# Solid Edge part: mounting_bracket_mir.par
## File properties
Author: Haley
Template: Metric Part.par
Last saved by: Lee
Revision: 3
Application: Solid Edge
Accuracy: 0.990
Username: Haley
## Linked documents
mounting_bracket.par
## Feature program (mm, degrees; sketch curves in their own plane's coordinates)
part copy "CopiedPart_1"
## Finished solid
Body 1: solid body, 21 faces, 44 edges, 24 vertices.
  Faces by surface: cylinder 10, torus 6, plane 5
  Edges by curve: circle 22, line 18, intersection 4
Bounding box of the edges (mm; curved faces can reach further): 152.400 x 38.100 x 119.538, from (-76.2, -19.05, -101.6) to (76.2, 19.05, 17.9381).
Cylindrical faces by radius (mm): R5 x6, R12.7 x3, R875.4 x1
Toroidal faces (ring radius, tube radius in mm): R7.7 r5 x4, R15.2 r2.5 x2
Planar faces by outward normal: +x 1, +y 1, -x 1, -y 1, -z 1
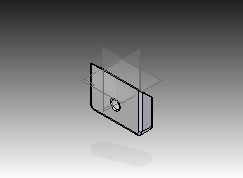
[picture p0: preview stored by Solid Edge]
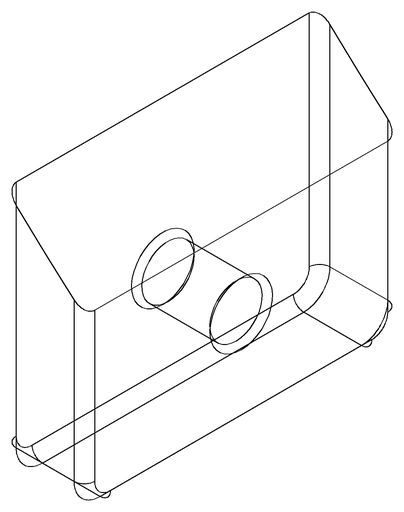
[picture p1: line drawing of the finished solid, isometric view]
